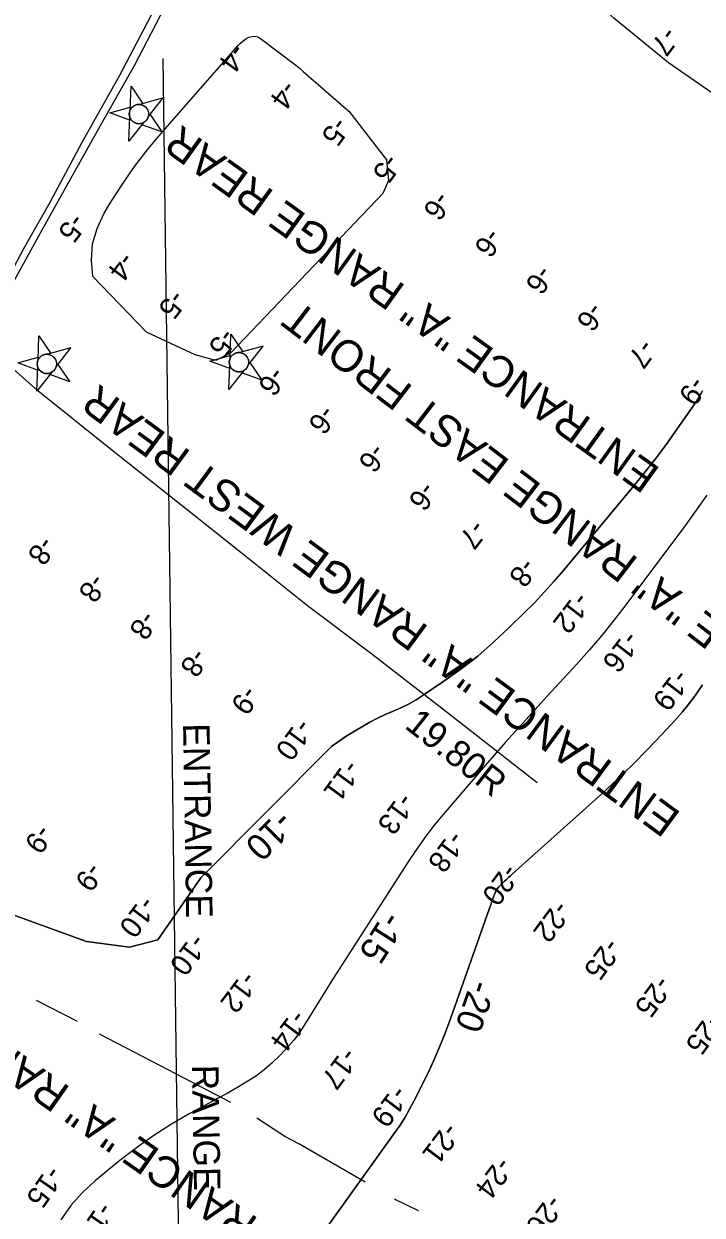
# Model space of a CAD drawing. Extents: x 3879599 to 3900814, y 146526 to 168888.
# Drawn here: x 3889001 to 3890077, y 154174 to 156064 of the extents above; entities that cross this region are included whole.
import ezdxf

# ---------------------------------------------------------------- set-up
doc = ezdxf.new("R2010")
doc.units = 0
for name, color, linetype in [('V-CHAN-NAID', 7, 'Continuous'), ('V-LEVE-TOET', 7, 'Continuous'), ('V-RIVR-JETY', 7, 'Continuous'), ('V-RIVR-RANG', 7, 'Continuous'), ('V-STRM-FMON', 7, 'Continuous'), ('V-TOPO-DPTH', 7, 'Continuous'), ('V-TOPO-MINR', 7, 'Continuous'), ('V-TOPO-MINR-IDEN', 7, 'Continuous')]:
    doc.layers.add(name, color=color, linetype=linetype)

msp = doc.modelspace()

# ---------------------------------------------------------------- linework, layer by layer
at = {"layer": 'V-CHAN-NAID'}
for points in [[(3889169.8, 155926.7), (3889171.3, 155964.9), (3889189.9, 155937.1), (3889185.3, 155935.8), (3889184.7, 155935.9), (3889183.6, 155935.9), (3889182.6, 155935.8), (3889181.6, 155935.7), (3889180.7, 155935.6), (3889179.8, 155935.3), (3889178.9, 155935.1), (3889178, 155934.7), (3889177.1, 155934.3), (3889176.3, 155933.9), (3889175.6, 155933.5), (3889174.9, 155933), (3889174, 155932.3), (3889173.4, 155931.8), (3889172.7, 155931.1), (3889172.2, 155930.5), (3889171.6, 155929.7), (3889171.1, 155929.1), (3889170.7, 155928.3), (3889170.2, 155927.5)], [(3889198.5, 155916.2), (3889222.1, 155946.3), (3889185.3, 155935.8), (3889186.4, 155935.7), (3889187.3, 155935.5), (3889188.3, 155935.2), (3889189.3, 155934.9), (3889190, 155934.6), (3889190.7, 155934.3), (3889191.4, 155933.9), (3889192.1, 155933.5), (3889192.8, 155933), (3889193.4, 155932.5), (3889194.2, 155931.9), (3889194.8, 155931.3), (3889195.5, 155930.5), (3889196.1, 155929.7), (3889196.7, 155928.9), (3889197.2, 155928.1), (3889197.6, 155927.3), (3889197.9, 155926.5), (3889198.3, 155925.6), (3889198.6, 155924.7), (3889198.7, 155923.9), (3889198.9, 155923.2), (3889199, 155922.3), (3889199.1, 155921.5), (3889199.1, 155920.4), (3889199.1, 155919.7), (3889199, 155918.7), (3889198.8, 155917.7), (3889198.7, 155916.9)], [(3889169.4, 155915.6), (3889169.2, 155910.8), (3889137.8, 155922.4), (3889170, 155931.5), (3889169.8, 155926.7), (3889169.5, 155925.9), (3889169.2, 155925.1), (3889168.9, 155924), (3889168.8, 155923), (3889168.6, 155921.9), (3889168.6, 155920.9), (3889168.6, 155919.9), (3889168.7, 155919), (3889168.8, 155918), (3889169, 155917.1), (3889169.2, 155916.2)], [(3889191.6, 155907.5), (3889168, 155877.4), (3889169.4, 155915.6), (3889169.7, 155914.8), (3889170.2, 155913.9), (3889170.6, 155913.1), (3889171.1, 155912.2), (3889171.6, 155911.4), (3889172.2, 155910.8), (3889172.9, 155910), (3889173.4, 155909.5), (3889174.3, 155908.7), (3889175.1, 155908.1), (3889176, 155907.5), (3889176.8, 155907.1), (3889177.8, 155906.6), (3889178.9, 155906.2), (3889179.9, 155905.9), (3889180.6, 155905.7), (3889181.7, 155905.5), (3889182.7, 155905.4), (3889183.8, 155905.4), (3889184.8, 155905.4), (3889185.7, 155905.5), (3889186.8, 155905.6), (3889187.9, 155905.9), (3889188.9, 155906.2), (3889189.9, 155906.6), (3889190.6, 155907)], [(3889198.5, 155916.2), (3889201.4, 155920), (3889220, 155892.2), (3889188.6, 155903.7), (3889191.6, 155907.5), (3889192.3, 155907.9), (3889193.2, 155908.6), (3889194, 155909.2), (3889194.7, 155909.9), (3889195.1, 155910.4), (3889195.7, 155910.9), (3889196.2, 155911.6), (3889196.6, 155912.2), (3889197.1, 155913), (3889197.4, 155913.6), (3889197.8, 155914.4), (3889198.1, 155915.2), (3889198.3, 155915.7)], [(3889023.8, 155530.4), (3889025.2, 155568.6), (3889043.9, 155540.8), (3889039.3, 155539.5), (3889038.7, 155539.5), (3889037.5, 155539.5), (3889036.6, 155539.5), (3889035.5, 155539.4), (3889034.6, 155539.2), (3889033.7, 155539), (3889032.9, 155538.7), (3889032, 155538.4), (3889031.1, 155538), (3889030.2, 155537.5), (3889029.6, 155537.1), (3889028.9, 155536.7), (3889028, 155535.9), (3889027.4, 155535.4), (3889026.6, 155534.7), (3889026.1, 155534.1), (3889025.6, 155533.4), (3889025.1, 155532.7), (3889024.6, 155532), (3889024.2, 155531.1)], [(3889328.3, 155533), (3889329.7, 155571.3), (3889348.3, 155543.5), (3889343.7, 155542.2), (3889343.1, 155542.2), (3889342, 155542.2), (3889341.1, 155542.2), (3889340, 155542.1), (3889339.1, 155541.9), (3889338.2, 155541.7), (3889337.4, 155541.4), (3889336.4, 155541.1), (3889335.6, 155540.7), (3889334.7, 155540.2), (3889334, 155539.8), (3889333.3, 155539.3), (3889332.4, 155538.6), (3889331.8, 155538.1), (3889331.1, 155537.4), (3889330.6, 155536.8), (3889330, 155536.1), (3889329.5, 155535.4), (3889329.1, 155534.7), (3889328.6, 155533.8)], [(3889052.4, 155519.8), (3889076, 155549.9), (3889039.3, 155539.5), (3889040.4, 155539.3), (3889041.2, 155539.2), (3889042.3, 155538.9), (3889043.3, 155538.5), (3889043.9, 155538.3), (3889044.7, 155537.9), (3889045.3, 155537.6), (3889046, 155537.2), (3889046.7, 155536.7), (3889047.4, 155536.2), (3889048.2, 155535.5), (3889048.7, 155534.9), (3889049.5, 155534.1), (3889050.1, 155533.3), (3889050.7, 155532.5), (3889051.1, 155531.7), (3889051.5, 155531), (3889051.9, 155530.2), (3889052.3, 155529.2), (3889052.5, 155528.4), (3889052.7, 155527.6), (3889052.9, 155526.8), (3889053, 155525.9), (3889053, 155525.2), (3889053.1, 155524.1), (3889053, 155523.3), (3889053, 155522.4), (3889052.8, 155521.4), (3889052.6, 155520.6)], [(3889356.9, 155522.5), (3889380.5, 155552.6), (3889343.7, 155542.2), (3889344.8, 155542), (3889345.7, 155541.8), (3889346.7, 155541.6), (3889347.8, 155541.2), (3889348.4, 155540.9), (3889349.1, 155540.6), (3889349.8, 155540.2), (3889350.5, 155539.8), (3889351.2, 155539.3), (3889351.8, 155538.9), (3889352.6, 155538.2), (3889353.2, 155537.6), (3889354, 155536.8), (3889354.6, 155536), (3889355.1, 155535.2), (3889355.6, 155534.4), (3889356, 155533.6), (3889356.4, 155532.9), (3889356.7, 155531.9), (3889357, 155531), (3889357.2, 155530.3), (3889357.3, 155529.5), (3889357.5, 155528.6), (3889357.5, 155527.9), (3889357.5, 155526.8), (3889357.5, 155526), (3889357.4, 155525), (3889357.3, 155524.1), (3889357.1, 155523.3)], [(3889023.4, 155519.3), (3889023.2, 155514.5), (3888991.8, 155526), (3889024, 155535.1), (3889023.8, 155530.4), (3889023.5, 155529.6), (3889023.2, 155528.7), (3889022.9, 155527.6), (3889022.7, 155526.7), (3889022.6, 155525.6), (3889022.5, 155524.5), (3889022.6, 155523.5), (3889022.6, 155522.7), (3889022.8, 155521.7), (3889022.9, 155520.8), (3889023.2, 155519.9)], [(3889327.8, 155522), (3889327.7, 155517.2), (3889296.3, 155528.7), (3889328.4, 155537.8), (3889328.3, 155533), (3889327.9, 155532.2), (3889327.7, 155531.4), (3889327.4, 155530.3), (3889327.2, 155529.3), (3889327.1, 155528.3), (3889327, 155527.2), (3889327, 155526.2), (3889327.1, 155525.3), (3889327.2, 155524.3), (3889327.4, 155523.4), (3889327.6, 155522.6)], [(3889045.6, 155511.1), (3889021.9, 155481.1), (3889023.4, 155519.3), (3889023.7, 155518.5), (3889024.1, 155517.5), (3889024.5, 155516.7), (3889025.1, 155515.8), (3889025.6, 155515.1), (3889026.1, 155514.4), (3889026.8, 155513.7), (3889027.4, 155513.1), (3889028.2, 155512.4), (3889029, 155511.8), (3889030, 155511.2), (3889030.8, 155510.7), (3889031.8, 155510.2), (3889032.8, 155509.8), (3889033.8, 155509.5), (3889034.6, 155509.3), (3889035.7, 155509.2), (3889036.7, 155509.1), (3889037.7, 155509), (3889038.7, 155509), (3889039.7, 155509.1), (3889040.8, 155509.3), (3889041.8, 155509.6), (3889042.8, 155509.9), (3889043.9, 155510.3), (3889044.6, 155510.6)], [(3889052.4, 155519.8), (3889055.4, 155523.6), (3889074, 155495.8), (3889042.6, 155507.4), (3889045.6, 155511.1), (3889046.3, 155511.6), (3889047.2, 155512.2), (3889048, 155512.9), (3889048.7, 155513.6), (3889049.1, 155514), (3889049.6, 155514.6), (3889050.1, 155515.3), (3889050.5, 155515.8), (3889051, 155516.7), (3889051.4, 155517.3), (3889051.8, 155518.1), (3889052.1, 155518.8), (3889052.3, 155519.3)], [(3889350, 155513.8), (3889326.4, 155483.7), (3889327.8, 155522), (3889328.1, 155521.1), (3889328.6, 155520.2), (3889329, 155519.4), (3889329.5, 155518.5), (3889330.1, 155517.8), (3889330.6, 155517.1), (3889331.3, 155516.3), (3889331.8, 155515.8), (3889332.7, 155515.1), (3889333.5, 155514.4), (3889334.4, 155513.8), (3889335.2, 155513.4), (3889336.3, 155512.9), (3889337.3, 155512.5), (3889338.3, 155512.2), (3889339.1, 155512), (3889340.1, 155511.8), (3889341.1, 155511.7), (3889342.2, 155511.7), (3889343.2, 155511.7), (3889344.1, 155511.8), (3889345.2, 155512), (3889346.3, 155512.2), (3889347.3, 155512.5), (3889348.3, 155512.9), (3889349.1, 155513.3)], [(3889356.9, 155522.5), (3889359.8, 155526.3), (3889378.5, 155498.5), (3889347.1, 155510), (3889350, 155513.8), (3889350.7, 155514.3), (3889351.6, 155514.9), (3889352.4, 155515.6), (3889353.2, 155516.3), (3889353.6, 155516.7), (3889354.1, 155517.3), (3889354.6, 155518), (3889355, 155518.5), (3889355.5, 155519.3), (3889355.8, 155519.9), (3889356.2, 155520.8), (3889356.5, 155521.5), (3889356.7, 155522)]]:
    msp.add_lwpolyline(points, close=True, dxfattribs=at)
for centre in [(3889183.8, 155920.6), (3889037.8, 155524.3), (3889342.3, 155527)]:
    msp.add_circle(centre, 15.3, dxfattribs=at)
at = {"layer": 'V-LEVE-TOET'}
for p, q in [((3889086.3, 154481), (3889021.6, 154514.4)), ((3889627.1, 154181.1), (3889589.1, 154199.5))]:
    msp.add_line(p, q, dxfattribs=at)
for points in [[(3890403.6, 155730.2), (3890324.9, 155789.6), (3890228.5, 155859.5), (3890140.2, 155921.2), (3890023.2, 156001.7), (3889936.4, 156072.9), (3889903.3, 156102.9), (3889830, 156175.1), (3889749.8, 156256.5), (3889673, 156327.5), (3889604.8, 156383.4), (3889506.1, 156470.1), (3889457.7, 156508.3)], [(3889814.8, 154859.8), (3889673.1, 154970.8), (3889552.8, 155064), (3889451.2, 155140.7), (3889345.4, 155224.9), (3889250.1, 155300.5), (3889138.3, 155389.8), (3889023.6, 155481.6), (3888930.9, 155563.5)], [(3889329.5, 154352.8), (3889216.8, 154411.6), (3889121.4, 154461)], [(3889542.2, 154226.2), (3889438.3, 154286.7), (3889414.9, 154298.9), (3889370.8, 154327.6)]]:
    msp.add_lwpolyline(points, dxfattribs=at)
at = {"layer": 'V-RIVR-JETY'}
for points in [[(3890041.5, 157361.1), (3889952, 157230.2), (3889885, 157127), (3889804.4, 157007.3), (3889729.7, 156906.4), (3889665.7, 156818.9), (3889564.1, 156678.4), (3889510.3, 156604.6), (3889453.5, 156501.9), (3889376.4, 156373.6), (3889299.8, 156235.8), (3889237.6, 156115.6), (3889176.7, 155998.2), (3889122.2, 155901.8), (3889067.7, 155804.7), (3889024.5, 155726.9), (3888970.4, 155628.7)], [(3888957.2, 155625.1), (3889001.4, 155707.5), (3889043, 155781.1), (3889093.3, 155875), (3889153.3, 155982.3), (3889225.3, 156120), (3889281.1, 156223.4), (3889371.8, 156382.6), (3889434.5, 156487.4), (3889446.7, 156513), (3889491, 156591.5), (3889508.1, 156616.8), (3889552.9, 156681.4), (3889608.3, 156758), (3889672.4, 156840.3), (3889725, 156918.2), (3889760.3, 156965.6), (3889818.4, 157051.6), (3889860.1, 157114.1), (3889946.9, 157242.3), (3890015.4, 157336.1)]]:
    msp.add_lwpolyline(points, dxfattribs=at)
at = {"layer": 'V-RIVR-RANG'}
msp.add_lwpolyline([(3889221.4, 156009), (3889317.4, 148746.9)], dxfattribs=at)
at = {"layer": 'V-TOPO-DPTH'}
for points in [[(3888957.4, 154660.1), (3889100.6, 154607.9), (3889168.9, 154599), (3889213.5, 154610.9), (3889281.9, 154709), (3889489.2, 154917.2), (3889512.3, 154933.6), (3889538.2, 154949.3), (3889550, 154956.1), (3889561.9, 154962.4), (3889574.2, 154968.1), (3889586.7, 154973.5), (3889599.1, 154978.9), (3889611.2, 154984.8), (3889623, 154991.5), (3889634.4, 154998.7), (3889667.3, 155021), (3889694.4, 155040.4), (3889720.8, 155060.9), (3889745.9, 155082.7), (3889770.3, 155105.4), (3889794.7, 155129.4), (3889810.6, 155145.5), (3889826.2, 155162), (3889841.3, 155178.9), (3889856.1, 155196.1), (3889965.6, 155327.5), (3889984.2, 155350.4), (3890002.4, 155373.6), (3890020, 155397.2), (3890037.2, 155421.2), (3890063.4, 155458.6), (3890067.1, 155464.1), (3890070.6, 155469.8), (3890073.9, 155475.6), (3890076.9, 155481.6)], [(3890076.9, 155015), (3890066.9, 155000.3), (3890056.4, 154986), (3890045.2, 154972.3), (3890033.4, 154958.9), (3890012.3, 154936.1), (3889989.4, 154912), (3889966, 154888.2), (3889942, 154865.2), (3889917.5, 154842.5), (3889776.1, 154715.2), (3889772.9, 154712.3), (3889769.7, 154709.5), (3889766.6, 154706.6), (3889763.4, 154703.7), (3889760.1, 154700.7), (3889757.2, 154697.8), (3889754.4, 154694.9), (3889751.8, 154691.8), (3889749.7, 154688.2), (3889748.8, 154686.3), (3889747.2, 154682.4), (3889746.4, 154680.5), (3889744.9, 154676), (3889743.4, 154671.9), (3889741.9, 154667.7), (3889740.5, 154663.5), (3889739, 154659.3), (3889678.2, 154487.1), (3889668, 154460), (3889657.2, 154433.1), (3889645.3, 154406.6), (3889632.7, 154380.5), (3889619.7, 154354.8), (3889612.9, 154341.9), (3889605.6, 154329.2), (3889597.7, 154316.9), (3889589.5, 154304.9), (3889363.9, 153989.9)], [(3889363.9, 153989.9), (3889589.5, 154304.9), (3889597.7, 154316.9), (3889605.6, 154329.2), (3889612.9, 154341.9), (3889619.7, 154354.8), (3889632.7, 154380.5), (3889645.3, 154406.6), (3889657.2, 154433.1), (3889668, 154460), (3889678.2, 154487.1), (3889739, 154659.3), (3889740.5, 154663.5), (3889741.9, 154667.7), (3889743.4, 154671.9), (3889744.9, 154676), (3889746.4, 154680.5), (3889747.2, 154682.4), (3889748.8, 154686.3), (3889749.7, 154688.2), (3889751.8, 154691.8), (3889754.4, 154694.9), (3889757.2, 154697.8), (3889760.1, 154700.7), (3889763.4, 154703.7), (3889766.6, 154706.6), (3889769.7, 154709.5), (3889772.9, 154712.3), (3889776.1, 154715.2), (3889917.5, 154842.5), (3889942, 154865.2), (3889966, 154888.2), (3889989.4, 154912), (3890012.3, 154936.1), (3890033.4, 154958.9), (3890045.2, 154972.3), (3890056.4, 154986), (3890066.9, 155000.3), (3890076.9, 155015)]]:
    msp.add_lwpolyline(points, dxfattribs=at)
at = {"layer": 'V-TOPO-MINR'}
msp.add_lwpolyline([(3889329.5, 155541.8), (3889305.7, 155529.9), (3889273, 155538.8), (3889195.7, 155574.5), (3889110.5, 155662.8), (3889108.5, 155689.1), (3889110.2, 155714.7), (3889117.5, 155739.3), (3889128.5, 155763.2), (3889137.3, 155777.9), (3889156.5, 155808), (3889176.8, 155837.4), (3889198.6, 155865.6), (3889221.5, 155893.1), (3889341.2, 156029.4), (3889345, 156033.2), (3889349, 156036.7), (3889353.4, 156039.7), (3889358.1, 156042.4), (3889362.9, 156043.8), (3889367.6, 156044.2), (3889372.1, 156043), (3889376.6, 156040.7), (3889432.6, 155998.2), (3889435, 155996.3), (3889437.4, 155994.3), (3889439.8, 155992.3), (3889442.1, 155990.3), (3889444.2, 155988), (3889516.7, 155925.4), (3889576.2, 155848.1), (3889579.2, 155815.4), (3889570.2, 155794.6)], close=True, dxfattribs=at)
for points in [[(3890076.9, 155481.6), (3890073.9, 155475.6), (3890070.6, 155469.8), (3890067.1, 155464.1), (3890063.4, 155458.6), (3890037.2, 155421.2), (3890020, 155397.2), (3890002.4, 155373.6), (3889984.2, 155350.4), (3889965.6, 155327.5), (3889856.1, 155196.1), (3889841.3, 155178.9), (3889826.2, 155162), (3889810.6, 155145.5), (3889794.7, 155129.4), (3889770.3, 155105.4), (3889745.9, 155082.7), (3889720.8, 155060.9), (3889694.4, 155040.4), (3889667.3, 155021), (3889634.4, 154998.7), (3889623, 154991.5), (3889611.2, 154984.8), (3889599.1, 154978.9), (3889586.7, 154973.5), (3889574.2, 154968.1), (3889561.9, 154962.4), (3889550, 154956.1), (3889538.2, 154949.3), (3889512.3, 154933.6), (3889489.2, 154917.2), (3889281.9, 154709), (3889213.5, 154610.9), (3889168.9, 154599), (3889100.6, 154607.9), (3888957.4, 154660.1)], [(3890084.1, 155316.1), (3890067.3, 155292.3), (3890050, 155268.7), (3889953.8, 155139.8), (3889935.5, 155116.1), (3889916.8, 155092.7), (3889897.3, 155070), (3889877.4, 155047.7), (3889830.3, 154996.6), (3889797.4, 154960.5), (3889764.8, 154924.1), (3889732.6, 154887.3), (3889700.7, 154850.3), (3889665.8, 154809.4), (3889651.9, 154792.4), (3889638.4, 154775.1), (3889625.7, 154757.1), (3889613.4, 154738.9), (3889502.3, 154565.8), (3889490.8, 154547.9), (3889479.5, 154529.9), (3889468.2, 154511.9), (3889457.1, 154493.8), (3889442.4, 154469.9), (3889438.5, 154463.9), (3889434.3, 154458), (3889429.7, 154452.3), (3889425, 154446.9), (3889407.5, 154428), (3889395.2, 154415.8), (3889382.2, 154404.4), (3889368.3, 154394.2), (3889353.8, 154384.7), (3889338.7, 154375.9), (3889323.6, 154367.2), (3889308.3, 154358.8), (3889293, 154350.4), (3889264.5, 154335.1), (3889235.5, 154318.3), (3889207.2, 154300.5), (3889179.9, 154281), (3889153.3, 154260.5), (3889114.7, 154228.9), (3889094.3, 154209.8), (3889075.8, 154189.3), (3889060.1, 154166.6)], [(3890076.9, 155015), (3890066.9, 155000.3), (3890056.4, 154986), (3890045.2, 154972.3), (3890033.4, 154958.9), (3890012.3, 154936.1), (3889989.4, 154912), (3889966, 154888.2), (3889942, 154865.2), (3889917.5, 154842.5), (3889776.1, 154715.2), (3889772.9, 154712.3), (3889769.7, 154709.5), (3889766.6, 154706.6), (3889763.4, 154703.7), (3889760.1, 154700.7), (3889757.2, 154697.8), (3889754.4, 154694.9), (3889751.8, 154691.8), (3889749.7, 154688.2), (3889748.8, 154686.3), (3889747.2, 154682.4), (3889746.4, 154680.5), (3889744.9, 154676), (3889743.4, 154671.9), (3889741.9, 154667.7), (3889740.5, 154663.5), (3889739, 154659.3), (3889678.2, 154487.1), (3889668, 154460), (3889657.2, 154433.1), (3889645.3, 154406.6), (3889632.7, 154380.5), (3889619.7, 154354.8), (3889612.9, 154341.9), (3889605.6, 154329.2), (3889597.7, 154316.9), (3889589.5, 154304.9), (3889363.9, 153989.9)]]:
    msp.add_lwpolyline(points, dxfattribs=at)

# ---------------------------------------------------------------- texts
at = {"layer": 'V-CHAN-NAID'}
for s, rotation, p in [('ENTRANCE "A" RANGE REAR', 144.3183, (3890012, 155357.4)), ('ENTRANCE "A" RANGE EAST FRONT', 142.6154, (3890372.4, 154912.4)), ('ENTRANCE "A" RANGE WEST REAR', 143.5972, (3890044.8, 154811.2)), ('ENTRANCE "A" RANGE EAST FRONT PASSING (-20.1)', 145.0553, (3889484.3, 154091)), ('ENTRANCE "A" RANGE FRONT (-20.1)', 144.9757, (3889157.6, 154027.6))]:
    msp.add_text(s, height=50, rotation=rotation, dxfattribs=at).set_placement(p)
at = {"layer": 'V-RIVR-RANG'}
for s, rotation, p in [('-7', 233.3283, (3890017, 156061.6)), ('-4', 233.9383, (3889332.3, 156035.1)), ('-4', 233.9383, (3889413.3, 155976.4)), ('-5', 233.9383, (3889494.8, 155918.5)), ('-5', 233.9383, (3889575.8, 155859.9)), ('-6', 233.9383, (3889656.3, 155800.5)), ('-5', 232.4783, (3889078, 155765.6)), ('-6', 233.9383, (3889737.3, 155741.9)), ('-4', 232.4783, (3889156.9, 155704.2)), ('-6', 233.9383, (3889818.3, 155683.2)), ('-5', 232.4783, (3889236.9, 155644.2)), ('-6', 233.9383, (3889899.2, 155624.5)), ('-5', 232.4783, (3889316.4, 155583.5)), ('-7', 233.9383, (3889980.2, 155565.9)), ('-6', 232.4783, (3889395.4, 155522.2)), ('-9', 233.9383, (3890061.1, 155507.1)), ('-6', 232.4783, (3889474.8, 155461.4)), ('-6', 232.4783, (3889554.3, 155400.7)), ('-6', 232.4783, (3889633.7, 155340)), ('-7', 232.4783, (3889713.2, 155279.3)), ('-8', 233.5583, (3889029.3, 155253.5)), ('-8', 232.4783, (3889792.8, 155218.8)), ('-8', 233.5583, (3889109.9, 155194.3)), ('-12', 232.4783, (3889877.6, 155165)), ('-8', 233.5583, (3889190.5, 155135.1)), ('-16', 232.4783, (3889956.2, 155103.2)), ('-8', 233.5583, (3889271.1, 155075.9)), ('-19', 232.4783, (3890035.6, 155042.4)), ('-9', 233.5583, (3889351.5, 155016.4)), ('-10', 233.5583, (3889436.9, 154963.8)), ('-11', 233.5583, (3889513.1, 154898.6)), ('-13', 233.5583, (3889598.8, 154846.3)), ('-9', 232.9683, (3889024.7, 154796.1)), ('-18', 233.5583, (3889678.6, 154786)), ('-9', 232.9683, (3889104.7, 154736.1)), ('-20', 233.5583, (3889764.3, 154733.7)), ('-10', 232.9683, (3889189.6, 154682.6)), ('-22', 233.5583, (3889845.4, 154675.3)), ('-10', 232.9683, (3889269.6, 154622.5)), ('-25', 233.5583, (3889925.7, 154615.6)), ('-12', 232.9683, (3889350.1, 154563.2)), ('-25', 233.5583, (3890006.3, 154556.4)), ('-14', 232.9683, (3889429.2, 154502)), ('-25', 233.5583, (3890086.9, 154497.2)), ('-17', 232.9683, (3889509.3, 154442.1)), ('-19', 232.9683, (3889589.2, 154382)), ('-21', 232.9683, (3889670.1, 154323.2)), ('-15', 235.1083, (3889040.5, 154254.6)), ('-24', 232.9683, (3889754.2, 154268.7)), ('-17', 235.1083, (3889122.2, 154197)), ('-26', 232.9683, (3889834.3, 154208.7))]:
    msp.add_text(s, height=33.5, rotation=rotation, dxfattribs=at).set_placement(p)
at = {"layer": 'V-STRM-FMON'}
for s, rotation, p in [('19.80R', 321.675, (3889603.2, 154947.9)), ('ENTRANCE', 270.9171, (3889253.7, 154954)), ('RANGE', 270.9171, (3889267.9, 154412.3))]:
    msp.add_text(s, height=42, rotation=rotation, dxfattribs=at).set_placement(p)
at = {"layer": 'V-TOPO-MINR-IDEN'}
for s, rotation, p in [('-10', 225.128, (3889405.9, 154818.9)), ('-15', 237.29, (3889574.3, 154658.8)), ('-20', 250.559, (3889711.3, 154549.6))]:
    msp.add_text(s, height=41.5, rotation=rotation, dxfattribs=at).set_placement(p)

doc.saveas('drawing.dxf')
